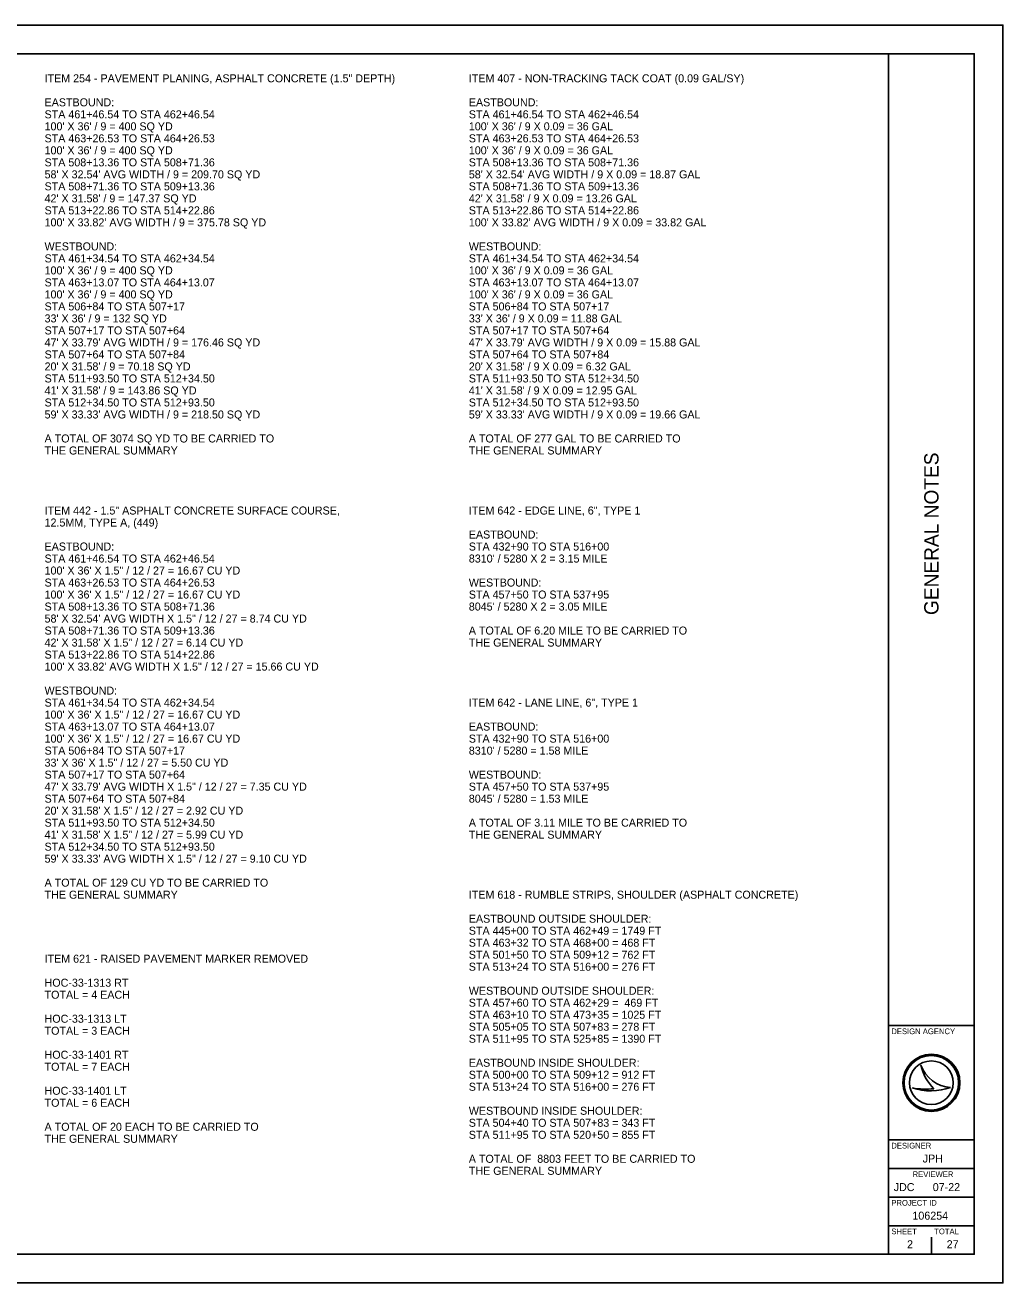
# Model space of a CAD drawing. Extents: x 0 to 34, y 0 to 22.
# Drawn here: x 16.9 to 34, y 0 to 22 of the extents above; entities that cross this region are included whole.
import ezdxf

# ---------------------------------------------------------------- set-up
doc = ezdxf.new("R2010")
doc.units = 0
for name, color, linetype in [('SH_Border', 7, 'Continuous'), ('SH_Cut_Line', 7, 'Continuous'), ('SH_Data', 7, 'Continuous'), ('SH_Text', 7, 'Continuous')]:
    doc.layers.add(name, color=color, linetype=linetype)

msp = doc.modelspace()

# ---------------------------------------------------------------- linework, layer by layer
at = {"layer": 'SH_Border'}
for p, q in [((32, 0.5), (32, 21.5)), ((32, 4.5), (33.5, 4.5)), ((32, 2.5), (33.5, 2.5)), ((32, 2), (33.5, 2)), ((32, 1.5), (33.5, 1.5)), ((32, 1), (33.5, 1))]:
    msp.add_line(p, q, dxfattribs=at)
msp.add_lwpolyline([(1.5, 21.5), (33.5, 21.5), (33.5, 0.5), (1.5, 0.5)], close=True, dxfattribs=at)
at = {"layer": 'SH_Cut_Line'}
msp.add_lwpolyline([(0, 0), (34, 0), (34, 22), (0, 22)], close=True, dxfattribs=at)
at = {"layer": 'SH_Data'}
for p, q in [((32.567, 3.81), (32.567, 3.81)), ((32.417, 3.41), (32.417, 3.41)), ((32.75, 3.5), (32.75, 3.5)), ((33.087, 3.419), (33.087, 3.419)), ((32.375, 0.675), (32.375, 0.675)), ((32.75, 0.5), (32.75, 0.8))]:
    msp.add_line(p, q, dxfattribs=at)
for radius in [0.5, 0.477, 0.477, 0.382]:
    msp.add_circle((32.75, 3.5), radius, dxfattribs=at)
for centre, radius, start, end in [((33.116, 3.998), 0.58, 198.9257, 198.9319), ((33.347, 3.97), 0.796, 191.6379, 191.6421), ((33.116, 3.998), 0.58, 198.9319, 267.1657), ((33.347, 3.97), 0.796, 191.6421, 226.0947), ((32.739, 4.37), 1.013, 251.4576, 290.0832), ((32.648, 4.654), 1.266, 259.4964, 259.4995), ((32.739, 4.37), 1.013, 251.4527, 251.4576), ((32.648, 4.654), 1.266, 259.4995, 276.6672)]:
    msp.add_arc(centre, radius, start, end, dxfattribs=at)

# ---------------------------------------------------------------- texts
msp.add_text('GENERAL NOTES', height=0.25, rotation=90, dxfattribs=at).set_placement((32.875, 11.682))
for s, height, p in [('DESIGN AGENCY', 0.1, (32.05, 4.35)), ('DESIGNER', 0.1, (32.05, 2.35)), ('JPH', 0.14, (32.598, 2.105)), ('REVIEWER', 0.1, (32.422, 1.85)), ('JDC', 0.14, (32.091, 1.605)), ('07-22', 0.14, (32.774, 1.605)), ('PROJECT ID', 0.1, (32.05, 1.35)), ('106254', 0.14, (32.418, 1.105)), ('SHEET', 0.1, (32.05, 0.85)), ('TOTAL', 0.1, (32.8, 0.85)), ('2', 0.14, (32.325, 0.605)), ('27', 0.14, (33.018, 0.605))]:
    msp.add_text(s, height=height, dxfattribs=at).set_placement(p)
at = {"layer": 'SH_Text'}
for s, p in [('ITEM 254 - PAVEMENT PLANING, ASPHALT CONCRETE (1.5" DEPTH)', (17.24, 21)), ('ITEM 407 - NON-TRACKING TACK COAT (0.09 GAL/SY)', (24.66, 21)), ('EASTBOUND:', (17.24, 20.58)), ('EASTBOUND:', (24.66, 20.58)), ('STA 461+46.54 TO STA 462+46.54', (17.24, 20.37)), ('STA 461+46.54 TO STA 462+46.54', (24.66, 20.37)), ("100' X 36' / 9 = 400 SQ YD", (17.24, 20.16)), ("100' X 36' / 9 X 0.09 = 36 GAL", (24.66, 20.16)), ('STA 463+26.53 TO STA 464+26.53', (17.24, 19.95)), ('STA 463+26.53 TO STA 464+26.53', (24.66, 19.95)), ("100' X 36' / 9 = 400 SQ YD", (17.24, 19.74)), ("100' X 36' / 9 X 0.09 = 36 GAL", (24.66, 19.74)), ('STA 508+13.36 TO STA 508+71.36', (17.24, 19.53)), ('STA 508+13.36 TO STA 508+71.36', (24.66, 19.53)), ("58' X 32.54' AVG WIDTH / 9 = 209.70 SQ YD", (17.24, 19.32)), ("58' X 32.54' AVG WIDTH / 9 X 0.09 = 18.87 GAL", (24.66, 19.32)), ('STA 508+71.36 TO STA 509+13.36', (17.24, 19.11)), ('STA 508+71.36 TO STA 509+13.36', (24.66, 19.11)), ("42' X 31.58' / 9 = 147.37 SQ YD", (17.24, 18.9)), ("42' X 31.58' / 9 X 0.09 = 13.26 GAL", (24.66, 18.9)), ('STA 513+22.86 TO STA 514+22.86', (17.24, 18.69)), ('STA 513+22.86 TO STA 514+22.86', (24.66, 18.69)), ("100' X 33.82' AVG WIDTH / 9 = 375.78 SQ YD", (17.24, 18.48)), ("100' X 33.82' AVG WIDTH / 9 X 0.09 = 33.82 GAL", (24.66, 18.48)), ('WESTBOUND:', (17.24, 18.06)), ('WESTBOUND:', (24.66, 18.06)), ('STA 461+34.54 TO STA 462+34.54', (17.24, 17.85)), ('STA 461+34.54 TO STA 462+34.54', (24.66, 17.85)), ("100' X 36' / 9 = 400 SQ YD", (17.24, 17.64)), ("100' X 36' / 9 X 0.09 = 36 GAL", (24.66, 17.64)), ('STA 463+13.07 TO STA 464+13.07', (17.24, 17.43)), ('STA 463+13.07 TO STA 464+13.07', (24.66, 17.43)), ("100' X 36' / 9 = 400 SQ YD", (17.24, 17.22)), ("100' X 36' / 9 X 0.09 = 36 GAL", (24.66, 17.22)), ("33' X 36' / 9 = 132 SQ YD", (17.24, 16.8)), ('STA 506+84 TO STA 507+17', (17.24, 17.01)), ("33' X 36' / 9 X 0.09 = 11.88 GAL", (24.66, 16.8)), ('STA 506+84 TO STA 507+17', (24.66, 17.01)), ('STA 507+17 TO STA 507+64', (17.24, 16.59)), ('STA 507+17 TO STA 507+64', (24.66, 16.59)), ("47' X 33.79' AVG WIDTH / 9 = 176.46 SQ YD", (17.24, 16.38)), ("47' X 33.79' AVG WIDTH / 9 X 0.09 = 15.88 GAL", (24.66, 16.38)), ('STA 507+64 TO STA 507+84', (17.24, 16.17)), ('STA 507+64 TO STA 507+84', (24.66, 16.17)), ("20' X 31.58' / 9 = 70.18 SQ YD", (17.24, 15.96)), ("20' X 31.58' / 9 X 0.09 = 6.32 GAL", (24.66, 15.96)), ('STA 511+93.50 TO STA 512+34.50', (17.24, 15.75)), ('STA 511+93.50 TO STA 512+34.50', (24.66, 15.75)), ("41' X 31.58' / 9 = 143.86 SQ YD", (17.24, 15.54)), ("41' X 31.58' / 9 X 0.09 = 12.95 GAL", (24.66, 15.54)), ('STA 512+34.50 TO STA 512+93.50', (17.24, 15.33)), ('STA 512+34.50 TO STA 512+93.50', (24.66, 15.33)), ("59' X 33.33' AVG WIDTH / 9 = 218.50 SQ YD", (17.24, 15.12)), ("59' X 33.33' AVG WIDTH / 9 X 0.09 = 19.66 GAL", (24.66, 15.12)), ('A TOTAL OF 3074 SQ YD TO BE CARRIED TO', (17.24, 14.7)), ('A TOTAL OF 277 GAL TO BE CARRIED TO', (24.66, 14.7)), ('THE GENERAL SUMMARY', (17.24, 14.49)), ('THE GENERAL SUMMARY', (24.66, 14.49)), ('ITEM 442 - 1.5" ASPHALT CONCRETE SURFACE COURSE,', (17.24, 13.44)), ('ITEM 642 - EDGE LINE, 6", TYPE 1', (24.66, 13.44)), ('12.5MM, TYPE A, (449)', (17.24, 13.23)), ('EASTBOUND:', (24.66, 13.02)), ('EASTBOUND:', (17.24, 12.81)), ('STA 432+90 TO STA 516+00', (24.66, 12.81)), ('STA 461+46.54 TO STA 462+46.54', (17.24, 12.6)), ("8310' / 5280 X 2 = 3.15 MILE", (24.66, 12.6)), ('STA 463+26.53 TO STA 464+26.53', (17.24, 12.18)), ('100\' X 36\' X 1.5" / 12 / 27 = 16.67 CU YD', (17.24, 12.39)), ('WESTBOUND:', (24.66, 12.18)), ('100\' X 36\' X 1.5" / 12 / 27 = 16.67 CU YD', (17.24, 11.97)), ('STA 457+50 TO STA 537+95', (24.66, 11.97)), ('STA 508+13.36 TO STA 508+71.36', (17.24, 11.76)), ("8045' / 5280 X 2 = 3.05 MILE", (24.66, 11.76)), ('58\' X 32.54\' AVG WIDTH X 1.5" / 12 / 27 = 8.74 CU YD', (17.24, 11.55)), ('STA 508+71.36 TO STA 509+13.36', (17.24, 11.34)), ('A TOTAL OF 6.20 MILE TO BE CARRIED TO', (24.66, 11.34)), ('42\' X 31.58\' X 1.5" / 12 / 27 = 6.14 CU YD', (17.24, 11.13)), ('THE GENERAL SUMMARY', (24.66, 11.13)), ('STA 513+22.86 TO STA 514+22.86', (17.24, 10.92)), ('100\' X 33.82\' AVG WIDTH X 1.5" / 12 / 27 = 15.66 CU YD', (17.24, 10.71)), ('WESTBOUND:', (17.24, 10.29)), ('STA 461+34.54 TO STA 462+34.54', (17.24, 10.08)), ('ITEM 642 - LANE LINE, 6", TYPE 1', (24.66, 10.08)), ('100\' X 36\' X 1.5" / 12 / 27 = 16.67 CU YD', (17.24, 9.87)), ('STA 463+13.07 TO STA 464+13.07', (17.24, 9.66)), ('EASTBOUND:', (24.66, 9.66)), ('100\' X 36\' X 1.5" / 12 / 27 = 16.67 CU YD', (17.24, 9.45)), ('STA 432+90 TO STA 516+00', (24.66, 9.45)), ('STA 506+84 TO STA 507+17', (17.24, 9.24)), ("8310' / 5280 = 1.58 MILE", (24.66, 9.24)), ('33\' X 36\' X 1.5" / 12 / 27 = 5.50 CU YD', (17.24, 9.03)), ('STA 507+17 TO STA 507+64', (17.24, 8.82)), ('WESTBOUND:', (24.66, 8.82)), ('47\' X 33.79\' AVG WIDTH X 1.5" / 12 / 27 = 7.35 CU YD', (17.24, 8.61)), ('STA 457+50 TO STA 537+95', (24.66, 8.61)), ('STA 507+64 TO STA 507+84', (17.24, 8.4)), ("8045' / 5280 = 1.53 MILE", (24.66, 8.4)), ('20\' X 31.58\' X 1.5" / 12 / 27 = 2.92 CU YD', (17.24, 8.19)), ('STA 511+93.50 TO STA 512+34.50', (17.24, 7.98)), ('A TOTAL OF 3.11 MILE TO BE CARRIED TO', (24.66, 7.98)), ('41\' X 31.58\' X 1.5" / 12 / 27 = 5.99 CU YD', (17.24, 7.77)), ('STA 512+34.50 TO STA 512+93.50', (17.24, 7.56)), ('THE GENERAL SUMMARY', (24.66, 7.77)), ('59\' X 33.33\' AVG WIDTH X 1.5" / 12 / 27 = 9.10 CU YD', (17.24, 7.35)), ('A TOTAL OF 129 CU YD TO BE CARRIED TO', (17.24, 6.93)), ('THE GENERAL SUMMARY', (17.24, 6.72)), ('ITEM 618 - RUMBLE STRIPS, SHOULDER (ASPHALT CONCRETE)', (24.66, 6.72)), ('EASTBOUND OUTSIDE SHOULDER:', (24.66, 6.3)), ('STA 445+00 TO STA 462+49 = 1749 FT', (24.66, 6.09)), ('STA 463+32 TO STA 468+00 = 468 FT', (24.66, 5.88)), ('ITEM 621 - RAISED PAVEMENT MARKER REMOVED', (17.24, 5.6)), ('STA 501+50 TO STA 509+12 = 762 FT', (24.66, 5.67)), ('STA 513+24 TO STA 516+00 = 276 FT', (24.66, 5.46)), ('HOC-33-1313 RT', (17.24, 5.18)), ('TOTAL = 4 EACH', (17.24, 4.97)), ('WESTBOUND OUTSIDE SHOULDER:', (24.66, 5.04)), ('STA 457+60 TO STA 462+29 =  469 FT', (24.66, 4.83)), ('HOC-33-1313 LT', (17.24, 4.55)), ('STA 463+10 TO STA 473+35 = 1025 FT', (24.66, 4.62)), ('TOTAL = 3 EACH', (17.24, 4.34)), ('STA 505+05 TO STA 507+83 = 278 FT', (24.66, 4.41)), ('STA 511+95 TO STA 525+85 = 1390 FT', (24.66, 4.2)), ('HOC-33-1401 RT', (17.24, 3.92)), ('TOTAL = 7 EACH', (17.24, 3.71)), ('EASTBOUND INSIDE SHOULDER:', (24.66, 3.78)), ('STA 500+00 TO STA 509+12 = 912 FT', (24.66, 3.57)), ('HOC-33-1401 LT', (17.24, 3.29)), ('STA 513+24 TO STA 516+00 = 276 FT', (24.66, 3.36)), ('TOTAL = 6 EACH', (17.24, 3.08)), ('WESTBOUND INSIDE SHOULDER:', (24.66, 2.94)), ('STA 504+40 TO STA 507+83 = 343 FT', (24.66, 2.73)), ('A TOTAL OF 20 EACH TO BE CARRIED TO', (17.24, 2.66)), ('STA 511+95 TO STA 520+50 = 855 FT', (24.66, 2.52)), ('THE GENERAL SUMMARY', (17.24, 2.45)), ('A TOTAL OF  8803 FEET TO BE CARRIED TO', (24.66, 2.1)), ('THE GENERAL SUMMARY', (24.66, 1.89))]:
    msp.add_text(s, height=0.14, dxfattribs=at).set_placement(p)

doc.saveas('drawing.dxf')
